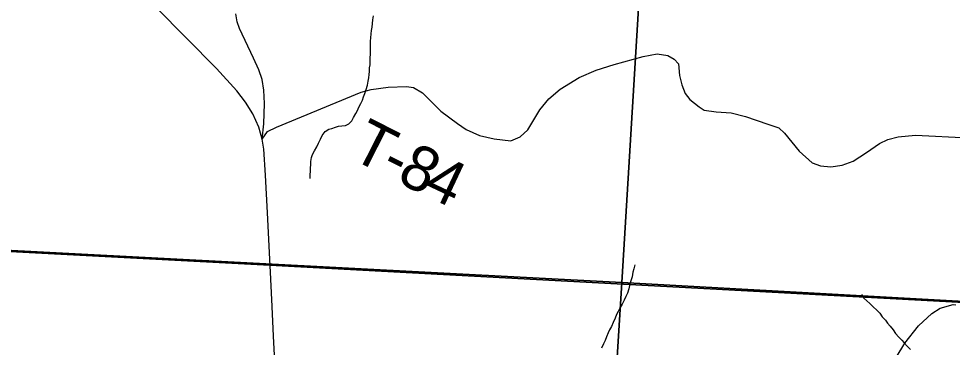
# Model space of a CAD drawing. Extents: x -20.2 to 34, y 0 to 22.
# Drawn here: x 6.216 to 7.395, y 18.889 to 19.304 of the extents above; entities that cross this region are included whole.
import ezdxf

# ---------------------------------------------------------------- set-up
doc = ezdxf.new("R2010")
doc.units = 0
for name, color, linetype in [('Default', 7, 'Continuous'), ('GM_X_County_Road', 7, 'Continuous'), ('GM_X_Minor_River', 7, 'Continuous'), ('GM_X_Section', 7, 'Continuous'), ('GM_X_Township_Road', 7, 'Continuous'), ('GM_X_Township_Road_Text', 7, 'Continuous')]:
    doc.layers.add(name, color=color, linetype=linetype)

msp = doc.modelspace()

# ---------------------------------------------------------------- linework, layer by layer
at = {"layer": 'Default'}
msp.add_lwpolyline([(8.1508, 20.9), (2.1, 20.9), (2.1, 19.2514), (2.9253, 19.1951), (4.084, 19.1299), (4.129, 19.1285), (4.5, 19.1063), (4.5753, 19.1032), (5.0716, 19.0751), (5.6168, 19.0426), (5.628, 19.0419), (5.9006, 19.026), (6.5332, 18.9927), (7.3871, 18.9465), (7.5395, 18.9382), (7.8072, 18.9199), (8.043, 18.9097), (8.0485, 19.0914), (8.0709, 19.4522), (8.1316, 20.5548)], close=True, dxfattribs=at)
msp.add_lwpolyline([(8.9, 14.8176), (8.9, 20.9), (8.1508, 20.9), (8.1316, 20.5548), (8.0709, 19.4522), (8.0485, 19.0914), (8.043, 18.9097), (7.8072, 18.9199), (7.5395, 18.9382), (7.3871, 18.9465), (6.5332, 18.9927), (5.9006, 19.026), (5.871, 18.5384), (5.8069, 17.4844), (5.7831, 17.2483), (5.7812, 17.1527), (5.7368, 16.4206)], dxfattribs=at)
at = {"layer": 'GM_X_County_Road'}
for points in [[(6.533, 19.0001), (6.53, 19.0588), (6.5275, 19.1064), (6.5255, 19.1392), (6.5244, 19.147), (6.5233, 19.1518), (6.5193, 19.1669), (6.5118, 19.184), (6.5025, 19.1988), (6.4916, 19.2128), (6.4656, 19.2411), (6.3894, 19.3181)], [(6.5233, 19.1518), (6.5255, 19.1714), (6.5263, 19.1968), (6.5255, 19.2139), (6.5235, 19.2271), (6.5191, 19.2397), (6.5126, 19.2542), (6.4946, 19.2916), (6.4919, 19.3002), (6.4902, 19.3105)], [(6.5106, 18.4875), (6.516, 18.5069), (6.5202, 18.5288), (6.5273, 18.5929), (6.5375, 18.6791), (6.5423, 18.7231), (6.5443, 18.7542), (6.544, 18.774), (6.5423, 18.8144), (6.5378, 18.9028), (6.5359, 18.9404), (6.5334, 18.9922), (6.5331, 18.9992), (6.533, 19.0001)]]:
    msp.add_lwpolyline(points, dxfattribs=at)
at = {"layer": 'GM_X_Minor_River'}
for points in [[(6.5842, 19.1021), (6.5841, 19.1066), (6.5844, 19.1112), (6.5844, 19.115), (6.5847, 19.12), (6.5847, 19.1238), (6.5857, 19.1287), (6.5872, 19.1325), (6.5894, 19.1371), (6.5924, 19.1421), (6.5946, 19.1467), (6.5972, 19.1517), (6.5991, 19.1566), (6.6032, 19.1616), (6.6077, 19.1643), (6.6115, 19.1655), (6.616, 19.1671), (6.6198, 19.1683), (6.624, 19.1687), (6.6285, 19.1691), (6.6327, 19.1711), (6.6368, 19.1749), (6.639, 19.1792), (6.6416, 19.1841), (6.6439, 19.1883), (6.6457, 19.1922), (6.6479, 19.1971), (6.6502, 19.201), (6.6516, 19.2052), (6.6531, 19.2097), (6.6546, 19.2147), (6.6564, 19.22), (6.6575, 19.225), (6.6582, 19.2296), (6.6585, 19.2334), (6.6589, 19.2372), (6.6592, 19.2421), (6.6599, 19.2459), (6.6598, 19.2512), (6.6598, 19.255), (6.6601, 19.2588), (6.6601, 19.2634), (6.6604, 19.2676), (6.6604, 19.2714), (6.6603, 19.2759), (6.6606, 19.2801), (6.6613, 19.2851), (6.6617, 19.2893), (6.6624, 19.2934), (6.6627, 19.298), (6.6634, 19.3026), (6.6641, 19.3079)], [(6.9943, 18.9929), (6.9928, 18.9879), (6.9917, 18.9837), (6.9907, 18.978), (6.9892, 18.9727), (6.9877, 18.9669), (6.9867, 18.9627), (6.9848, 18.957), (6.983, 18.9528), (6.9808, 18.9482), (6.9782, 18.9433), (6.9752, 18.9383), (6.973, 18.9341), (6.9711, 18.9302), (6.9693, 18.9257), (6.967, 18.9203), (6.9648, 18.915), (6.9622, 18.9108), (6.9604, 18.9069), (6.9585, 18.902), (6.9567, 18.8974), (6.9545, 18.8932), (6.9522, 18.8878)], [(7.2806, 18.9554), (7.2836, 18.9509), (7.2875, 18.9475), (7.2913, 18.9441), (7.2952, 18.94), (7.2998, 18.9355), (7.3036, 18.9318), (7.3067, 18.9272), (7.3109, 18.9231), (7.3136, 18.9193), (7.3167, 18.9156), (7.3206, 18.9107), (7.3237, 18.9062), (7.3279, 18.9017), (7.3317, 18.8979), (7.3344, 18.8942), (7.3383, 18.89), (7.3425, 18.8859)]]:
    msp.add_lwpolyline(points, dxfattribs=at)
at = {"layer": 'GM_X_Section'}
for points in [[(7.0409, 20.0115), (6.9777, 18.9706), (5.9253, 19.026), (5.9839, 20.0577)], [(8.0972, 19.9556), (8.0404, 18.9117), (6.9777, 18.9706), (7.0409, 20.0115)], [(5.9021, 19.0275), (5.9253, 19.026), (6.9777, 18.9706), (6.915, 17.9639), (5.8423, 18.0007)], [(6.9777, 18.9706), (8.0404, 18.9117), (7.9819, 17.9077), (6.915, 17.9639)]]:
    msp.add_lwpolyline(points, close=True, dxfattribs=at)
at = {"layer": 'GM_X_Township_Road'}
for points in [[(6.5233, 19.1518), (6.5303, 19.1616), (6.5415, 19.1669), (6.6483, 19.2111), (6.6612, 19.2145), (6.6828, 19.2176), (6.7059, 19.2186), (6.7147, 19.2172), (6.7259, 19.2104), (6.7493, 19.1872), (6.7701, 19.1718), (6.7811, 19.1641), (6.7981, 19.1565), (6.8167, 19.1521), (6.8374, 19.1499), (6.8492, 19.1547), (6.8589, 19.1636), (6.8742, 19.189), (6.8857, 19.2027), (6.9001, 19.215), (6.9241, 19.2298), (6.9453, 19.2392), (6.9682, 19.2461), (7.0047, 19.2562), (7.0226, 19.2597), (7.0358, 19.2576), (7.0441, 19.2529), (7.0492, 19.2472), (7.0507, 19.2324), (7.0535, 19.2206), (7.058, 19.2095), (7.0636, 19.2018), (7.0756, 19.1926), (7.082, 19.1887), (7.0968, 19.1865), (7.1161, 19.1853), (7.1341, 19.1806), (7.1621, 19.1707), (7.1762, 19.166), (7.1835, 19.1594), (7.2017, 19.1365), (7.2184, 19.1221), (7.229, 19.1181), (7.242, 19.1167), (7.2563, 19.1188), (7.27, 19.124), (7.287, 19.1349), (7.3032, 19.1462), (7.314, 19.1514), (7.327, 19.1549), (7.3489, 19.1568), (7.4156, 19.1535)], [(7.2548, 18.7814), (7.2648, 18.7897), (7.2783, 18.7972), (7.2921, 18.8041), (7.3017, 18.8102), (7.3101, 18.8379), (7.3147, 18.8567), (7.3246, 18.8757), (7.3353, 18.894), (7.3527, 18.9157), (7.3694, 18.9315), (7.3802, 18.9384), (7.3966, 18.9427), (7.3996, 18.9426)]]:
    msp.add_lwpolyline(points, dxfattribs=at)

# ---------------------------------------------------------------- texts
at = {"layer": 'GM_X_Township_Road_Text'}
for s, rotation, p in [('T', 333.065, (6.6328, 19.1288)), ('8', 333.2779, (6.6917, 19.0989)), ('-', 333.108, (6.6708, 19.1096)), ('4', 334.7949, (6.7245, 19.0825))]:
    msp.add_text(s, height=0.0568, rotation=rotation, dxfattribs=at).set_placement(p)

doc.saveas('drawing.dxf')
